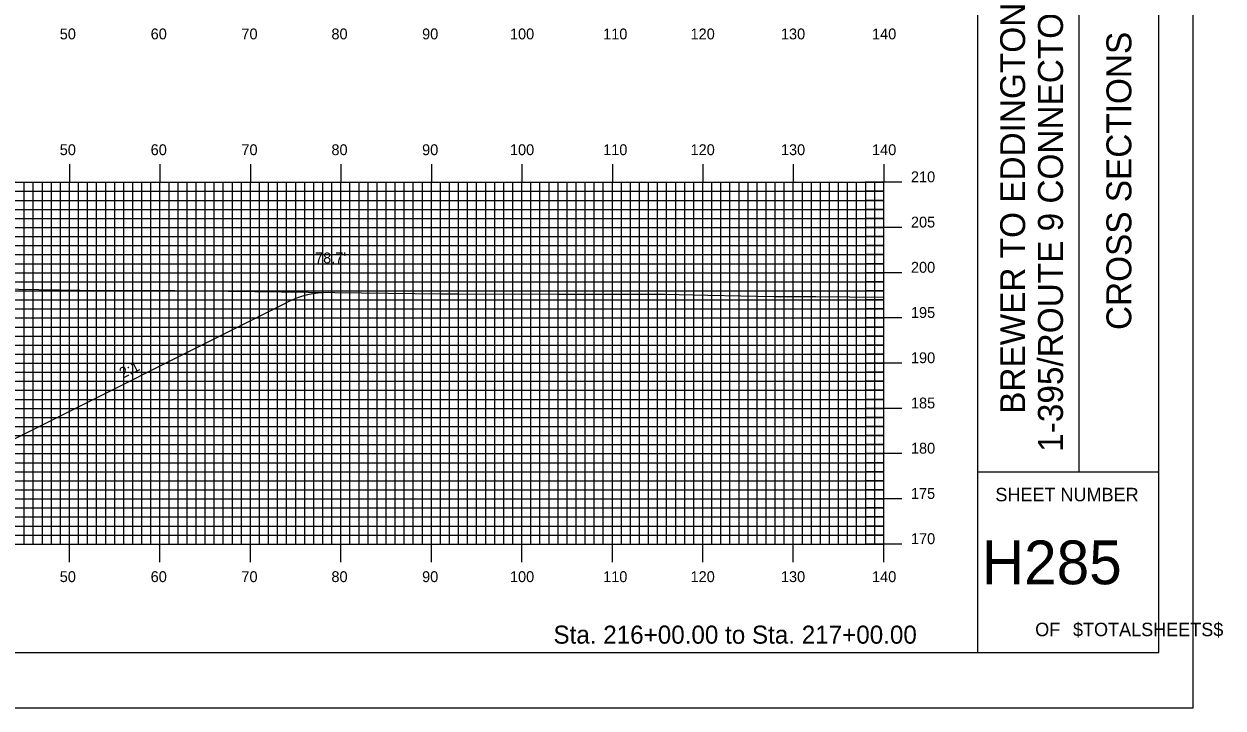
# Model space of a CAD drawing. Extents: x 1796420 to 1796763, y 442591 to 442811.
# Drawn here: x 1796630.9 to 1796763.4, y 442590.5 to 442666.2 of the extents above; entities that cross this region are included whole.
import ezdxf

# ---------------------------------------------------------------- set-up
doc = ezdxf.new("R2010")
doc.units = 0
for name, color, linetype in [('ANNOTATION', 7, 'Continuous'), ('BORDER', 7, 'Continuous'), ('D_Roadway_SlopeLines', 7, 'Continuous'), ('D_Text_Standard', 7, 'Continuous'), ('H_V ANNOTATION', 7, 'Continuous'), ('MAJOR', 7, 'Continuous'), ('MINOR', 7, 'Continuous'), ('PLOT BOUNDARY', 7, 'Continuous'), ('S_Roadway_Centerline', 7, 'Continuous')]:
    doc.layers.add(name, color=color, linetype=linetype)

msp = doc.modelspace()

# ---------------------------------------------------------------- linework, layer by layer
at = {"layer": 'ANNOTATION'}
msp.add_line((1796725.91, 442628.67), (1796725.91, 442629.27), dxfattribs=at)
msp.add_arc((1796664.49, 442626.48), 10, 89.621, 116.5651, dxfattribs=at)
msp.add_arc((1796664.49, 442626.48), 10, 89.621, 116.5651, dxfattribs=at)
at = {"layer": 'BORDER'}
for p, q in [((1796736.31, 442596.67), (1796736.31, 442806.67)), ((1796747.49, 442616.67), (1796747.49, 442686.67)), ((1796736.31, 442616.67), (1796756.31, 442616.67))]:
    msp.add_line(p, q, dxfattribs=at)
msp.add_lwpolyline([(1796436.31, 442596.67), (1796756.31, 442596.67), (1796756.31, 442806.67), (1796436.31, 442806.67)], close=True, dxfattribs=at)
at = {"layer": 'D_Roadway_SlopeLines'}
msp.add_lwpolyline([(1796621.3, 442619.07), (1796627.3, 442619.07), (1796660.02, 442635.43)], dxfattribs=at)
at = {"layer": 'MAJOR'}
for p, q in [((1796635.91, 442650.67), (1796635.91, 442648.67)), ((1796645.91, 442650.67), (1796645.91, 442648.67)), ((1796655.91, 442650.67), (1796655.91, 442648.67)), ((1796665.91, 442650.67), (1796665.91, 442648.67)), ((1796675.91, 442650.67), (1796675.91, 442648.67)), ((1796685.91, 442650.67), (1796685.91, 442648.67)), ((1796695.91, 442650.67), (1796695.91, 442648.67)), ((1796705.91, 442650.67), (1796705.91, 442648.67)), ((1796715.91, 442650.67), (1796715.91, 442648.67)), ((1796725.91, 442650.67), (1796725.91, 442648.67)), ((1796445.91, 442648.67), (1796725.91, 442648.67)), ((1796445.91, 442648.67), (1796725.91, 442648.67)), ((1796635.91, 442608.67), (1796635.91, 442648.67)), ((1796645.91, 442608.67), (1796645.91, 442648.67)), ((1796655.91, 442608.67), (1796655.91, 442648.67)), ((1796665.91, 442608.67), (1796665.91, 442648.67)), ((1796675.91, 442608.67), (1796675.91, 442648.67)), ((1796685.91, 442608.67), (1796685.91, 442648.67)), ((1796695.91, 442608.67), (1796695.91, 442648.67)), ((1796705.91, 442608.67), (1796705.91, 442648.67)), ((1796715.91, 442608.67), (1796715.91, 442648.67)), ((1796727.91, 442648.67), (1796723.9, 442648.67)), ((1796725.91, 442608.67), (1796725.91, 442648.67)), ((1796725.91, 442608.67), (1796725.91, 442648.67)), ((1796445.91, 442643.67), (1796725.91, 442643.67)), ((1796727.91, 442643.67), (1796723.9, 442643.67)), ((1796445.91, 442638.67), (1796725.91, 442638.67)), ((1796727.91, 442638.67), (1796723.9, 442638.67)), ((1796445.91, 442633.67), (1796725.91, 442633.67)), ((1796727.91, 442633.67), (1796723.9, 442633.67)), ((1796445.91, 442628.67), (1796725.91, 442628.67)), ((1796727.91, 442628.67), (1796723.9, 442628.67)), ((1796445.91, 442623.67), (1796725.91, 442623.67)), ((1796727.91, 442623.67), (1796723.9, 442623.67)), ((1796445.91, 442618.67), (1796725.91, 442618.67)), ((1796727.91, 442618.67), (1796723.9, 442618.67)), ((1796445.91, 442613.67), (1796725.91, 442613.67)), ((1796727.91, 442613.67), (1796723.9, 442613.67)), ((1796445.91, 442608.67), (1796725.91, 442608.67)), ((1796445.91, 442608.67), (1796725.91, 442608.67)), ((1796635.91, 442606.66), (1796635.91, 442608.67)), ((1796645.91, 442606.66), (1796645.91, 442608.67)), ((1796655.91, 442606.66), (1796655.91, 442608.67)), ((1796665.91, 442606.66), (1796665.91, 442608.67)), ((1796675.91, 442606.66), (1796675.91, 442608.67)), ((1796685.91, 442606.66), (1796685.91, 442608.67)), ((1796695.91, 442606.66), (1796695.91, 442608.67)), ((1796705.91, 442606.66), (1796705.91, 442608.67)), ((1796715.91, 442606.66), (1796715.91, 442608.67)), ((1796727.91, 442608.67), (1796723.9, 442608.67)), ((1796725.91, 442606.66), (1796725.91, 442608.67))]:
    msp.add_line(p, q, dxfattribs=at)
at = {"layer": 'MINOR'}
for p, q in [((1796630.91, 442608.67), (1796630.91, 442648.67)), ((1796631.91, 442608.67), (1796631.91, 442648.67)), ((1796632.91, 442608.67), (1796632.91, 442648.67)), ((1796633.91, 442608.67), (1796633.91, 442648.67)), ((1796634.91, 442608.67), (1796634.91, 442648.67)), ((1796636.91, 442608.67), (1796636.91, 442648.67)), ((1796637.91, 442608.67), (1796637.91, 442648.67)), ((1796638.91, 442608.67), (1796638.91, 442648.67)), ((1796639.91, 442608.67), (1796639.91, 442648.67)), ((1796640.91, 442608.67), (1796640.91, 442648.67)), ((1796641.91, 442608.67), (1796641.91, 442648.67)), ((1796642.91, 442608.67), (1796642.91, 442648.67)), ((1796643.91, 442608.67), (1796643.91, 442648.67)), ((1796644.91, 442608.67), (1796644.91, 442648.67)), ((1796646.91, 442608.67), (1796646.91, 442648.67)), ((1796647.91, 442608.67), (1796647.91, 442648.67)), ((1796648.91, 442608.67), (1796648.91, 442648.67)), ((1796649.91, 442608.67), (1796649.91, 442648.67)), ((1796650.91, 442608.67), (1796650.91, 442648.67)), ((1796651.91, 442608.67), (1796651.91, 442648.67)), ((1796652.91, 442608.67), (1796652.91, 442648.67)), ((1796653.91, 442608.67), (1796653.91, 442648.67)), ((1796654.91, 442608.67), (1796654.91, 442648.67)), ((1796656.91, 442608.67), (1796656.91, 442648.67)), ((1796657.91, 442608.67), (1796657.91, 442648.67)), ((1796658.91, 442608.67), (1796658.91, 442648.67)), ((1796659.91, 442608.67), (1796659.91, 442648.67)), ((1796660.91, 442608.67), (1796660.91, 442648.67)), ((1796661.91, 442608.67), (1796661.91, 442648.67)), ((1796662.91, 442608.67), (1796662.91, 442648.67)), ((1796663.91, 442608.67), (1796663.91, 442648.67)), ((1796664.91, 442608.67), (1796664.91, 442648.67)), ((1796666.91, 442608.67), (1796666.91, 442648.67)), ((1796667.91, 442608.67), (1796667.91, 442648.67)), ((1796668.91, 442608.67), (1796668.91, 442648.67)), ((1796669.91, 442608.67), (1796669.91, 442648.67)), ((1796670.91, 442608.67), (1796670.91, 442648.67)), ((1796671.91, 442608.67), (1796671.91, 442648.67)), ((1796672.91, 442608.67), (1796672.91, 442648.67)), ((1796673.91, 442608.67), (1796673.91, 442648.67)), ((1796674.91, 442608.67), (1796674.91, 442648.67)), ((1796676.91, 442608.67), (1796676.91, 442648.67)), ((1796677.91, 442608.67), (1796677.91, 442648.67)), ((1796678.91, 442608.67), (1796678.91, 442648.67)), ((1796679.91, 442608.67), (1796679.91, 442648.67)), ((1796680.91, 442608.67), (1796680.91, 442648.67)), ((1796681.91, 442608.67), (1796681.91, 442648.67)), ((1796682.91, 442608.67), (1796682.91, 442648.67)), ((1796683.91, 442608.67), (1796683.91, 442648.67)), ((1796684.91, 442608.67), (1796684.91, 442648.67)), ((1796686.91, 442608.67), (1796686.91, 442648.67)), ((1796687.91, 442608.67), (1796687.91, 442648.67)), ((1796688.91, 442608.67), (1796688.91, 442648.67)), ((1796689.91, 442608.67), (1796689.91, 442648.67)), ((1796690.91, 442608.67), (1796690.91, 442648.67)), ((1796691.91, 442608.67), (1796691.91, 442648.67)), ((1796692.91, 442608.67), (1796692.91, 442648.67)), ((1796693.91, 442608.67), (1796693.91, 442648.67)), ((1796694.91, 442608.67), (1796694.91, 442648.67)), ((1796696.91, 442608.67), (1796696.91, 442648.67)), ((1796697.91, 442608.67), (1796697.91, 442648.67)), ((1796698.91, 442608.67), (1796698.91, 442648.67)), ((1796699.91, 442608.67), (1796699.91, 442648.67)), ((1796700.91, 442608.67), (1796700.91, 442648.67)), ((1796701.91, 442608.67), (1796701.91, 442648.67)), ((1796702.91, 442608.67), (1796702.91, 442648.67)), ((1796703.91, 442608.67), (1796703.91, 442648.67)), ((1796704.91, 442608.67), (1796704.91, 442648.67)), ((1796706.91, 442608.67), (1796706.91, 442648.67)), ((1796707.91, 442608.67), (1796707.91, 442648.67)), ((1796708.91, 442608.67), (1796708.91, 442648.67)), ((1796709.91, 442608.67), (1796709.91, 442648.67)), ((1796710.91, 442608.67), (1796710.91, 442648.67)), ((1796711.91, 442608.67), (1796711.91, 442648.67)), ((1796712.91, 442608.67), (1796712.91, 442648.67)), ((1796713.91, 442608.67), (1796713.91, 442648.67)), ((1796714.91, 442608.67), (1796714.91, 442648.67)), ((1796716.91, 442608.67), (1796716.91, 442648.67)), ((1796717.91, 442608.67), (1796717.91, 442648.67)), ((1796718.91, 442608.67), (1796718.91, 442648.67)), ((1796719.91, 442608.67), (1796719.91, 442648.67)), ((1796720.91, 442608.67), (1796720.91, 442648.67)), ((1796721.91, 442608.67), (1796721.91, 442648.67)), ((1796722.91, 442608.67), (1796722.91, 442648.67)), ((1796723.91, 442608.67), (1796723.91, 442648.67)), ((1796724.91, 442608.67), (1796724.91, 442648.67)), ((1796445.91, 442647.67), (1796725.91, 442647.67)), ((1796725.91, 442647.67), (1796723.9, 442647.67)), ((1796445.91, 442646.67), (1796725.91, 442646.67)), ((1796725.91, 442646.67), (1796723.9, 442646.67)), ((1796445.91, 442645.67), (1796725.91, 442645.67)), ((1796725.91, 442645.67), (1796723.9, 442645.67)), ((1796445.91, 442644.67), (1796725.91, 442644.67)), ((1796725.91, 442644.67), (1796723.9, 442644.67)), ((1796445.91, 442642.67), (1796725.91, 442642.67)), ((1796725.91, 442642.67), (1796723.9, 442642.67)), ((1796445.91, 442641.67), (1796725.91, 442641.67)), ((1796725.91, 442641.67), (1796723.9, 442641.67)), ((1796445.91, 442640.67), (1796725.91, 442640.67)), ((1796445.91, 442639.67), (1796725.91, 442639.67)), ((1796725.91, 442640.67), (1796723.9, 442640.67)), ((1796725.91, 442639.67), (1796723.9, 442639.67)), ((1796445.91, 442637.67), (1796725.91, 442637.67)), ((1796725.91, 442637.67), (1796723.9, 442637.67)), ((1796445.91, 442636.67), (1796725.91, 442636.67)), ((1796445.91, 442635.67), (1796725.91, 442635.67)), ((1796725.91, 442636.67), (1796723.9, 442636.67)), ((1796725.91, 442635.67), (1796723.9, 442635.67)), ((1796445.91, 442634.67), (1796725.91, 442634.67)), ((1796725.91, 442634.67), (1796723.9, 442634.67)), ((1796445.91, 442632.67), (1796725.91, 442632.67)), ((1796445.91, 442631.67), (1796725.91, 442631.67)), ((1796725.91, 442632.67), (1796723.9, 442632.67)), ((1796725.91, 442631.67), (1796723.9, 442631.67)), ((1796445.91, 442630.67), (1796725.91, 442630.67)), ((1796725.91, 442630.67), (1796723.9, 442630.67)), ((1796445.91, 442629.67), (1796725.91, 442629.67)), ((1796725.91, 442629.67), (1796723.9, 442629.67)), ((1796445.91, 442627.67), (1796725.91, 442627.67)), ((1796725.91, 442627.67), (1796723.9, 442627.67)), ((1796445.91, 442626.67), (1796725.91, 442626.67)), ((1796725.91, 442626.67), (1796723.9, 442626.67)), ((1796445.91, 442625.67), (1796725.91, 442625.67)), ((1796725.91, 442625.67), (1796723.9, 442625.67)), ((1796445.91, 442624.67), (1796725.91, 442624.67)), ((1796725.91, 442624.67), (1796723.9, 442624.67)), ((1796445.91, 442622.67), (1796725.91, 442622.67)), ((1796725.91, 442622.67), (1796723.9, 442622.67)), ((1796445.91, 442621.67), (1796725.91, 442621.67)), ((1796725.91, 442621.67), (1796723.9, 442621.67)), ((1796445.91, 442620.67), (1796725.91, 442620.67)), ((1796445.91, 442619.67), (1796725.91, 442619.67)), ((1796725.91, 442620.67), (1796723.9, 442620.67)), ((1796725.91, 442619.67), (1796723.9, 442619.67)), ((1796445.91, 442617.67), (1796725.91, 442617.67)), ((1796725.91, 442617.67), (1796723.9, 442617.67)), ((1796445.91, 442616.67), (1796725.91, 442616.67)), ((1796445.91, 442615.67), (1796725.91, 442615.67)), ((1796725.91, 442616.67), (1796723.9, 442616.67)), ((1796725.91, 442615.67), (1796723.9, 442615.67)), ((1796445.91, 442614.67), (1796725.91, 442614.67)), ((1796725.91, 442614.67), (1796723.9, 442614.67)), ((1796445.91, 442612.67), (1796725.91, 442612.67)), ((1796445.91, 442611.67), (1796725.91, 442611.67)), ((1796725.91, 442612.67), (1796723.9, 442612.67)), ((1796725.91, 442611.67), (1796723.9, 442611.67)), ((1796445.91, 442610.67), (1796725.91, 442610.67)), ((1796725.91, 442610.67), (1796723.9, 442610.67)), ((1796445.91, 442609.67), (1796725.91, 442609.67)), ((1796725.91, 442609.67), (1796723.9, 442609.67))]:
    msp.add_line(p, q, dxfattribs=at)
at = {"layer": 'PLOT BOUNDARY'}
msp.add_lwpolyline([(1796420.12, 442590.55), (1796760.12, 442590.55), (1796760.12, 442810.55), (1796420.12, 442810.55)], close=True, dxfattribs=at)
at = {"layer": 'S_Roadway_Centerline'}
msp.add_lwpolyline([(1796621.2, 442636.99), (1796639.28, 442636.72), (1796642.75, 442636.73), (1796647.54, 442636.69), (1796659.34, 442636.55), (1796677.02, 442636.33), (1796678.85, 442636.32), (1796689.93, 442636.31), (1796698.54, 442636.3), (1796701.72, 442636.3), (1796706.47, 442636.2), (1796713.74, 442636.05), (1796718.41, 442636.04), (1796725.91, 442635.98)], dxfattribs=at)

# ---------------------------------------------------------------- texts
at = {"layer": 'ANNOTATION'}
msp.add_text('2:1', height=1.2, rotation=26.5651, dxfattribs=at).set_placement((1796641.79, 442626.95))
msp.add_text('2:1', height=1.2, rotation=26.5651, dxfattribs=at).set_placement((1796641.79, 442626.95))
at = {"layer": 'BORDER'}
for s, p in [('1-395/ROUTE 9 CONNECTOR', (1796745.71, 442618.87)), ('BREWER TO EDDINGTON', (1796741.53, 442623.07)), ('CROSS SECTIONS', (1796753.27, 442632.34))]:
    msp.add_text(s, height=2.7557, rotation=90, dxfattribs=at).set_placement(p)
for s, height, p in [('SHEET NUMBER', 1.4905, (1796738.24, 442613.4)), ('H285', 4.839, (1796736.74, 442604.23)), ('OF', 1.491, (1796742.64, 442598.49)), ('$TOTALSHEETS$', 1.4905, (1796746.82, 442598.49))]:
    msp.add_text(s, height=height, dxfattribs=at).set_placement(p)
at = {"layer": 'D_Text_Standard'}
msp.add_text("78.7'", height=1.2, dxfattribs=at).set_placement((1796663.05, 442639.71))
at = {"layer": 'H_V ANNOTATION'}
for s, height, p in [('50', 1.2, (1796634.83, 442664.47)), ('60', 1.2, (1796644.88, 442664.47)), ('70', 1.2, (1796654.91, 442664.47)), ('80', 1.2, (1796664.86, 442664.47)), ('90', 1.2, (1796674.88, 442664.47)), ('100', 1.2, (1796684.59, 442664.47)), ('110', 1.2, (1796694.89, 442664.47)), ('120', 1.2, (1796704.55, 442664.47)), ('130', 1.2, (1796714.54, 442664.47)), ('140', 1.2, (1796724.61, 442664.47)), ('50', 1.2, (1796634.83, 442651.67)), ('60', 1.2, (1796644.88, 442651.67)), ('70', 1.2, (1796654.91, 442651.67)), ('80', 1.2, (1796664.86, 442651.67)), ('90', 1.2, (1796674.88, 442651.67)), ('100', 1.2, (1796684.59, 442651.67)), ('110', 1.2, (1796694.89, 442651.67)), ('120', 1.2, (1796704.55, 442651.67)), ('130', 1.2, (1796714.54, 442651.67)), ('140', 1.2, (1796724.61, 442651.67)), ('210', 1.2, (1796728.91, 442648.67)), ('205', 1.2, (1796728.91, 442643.67)), ('200', 1.2, (1796728.91, 442638.67)), ('195', 1.2, (1796728.91, 442633.67)), ('190', 1.2, (1796728.91, 442628.67)), ('185', 1.2, (1796728.91, 442623.67)), ('180', 1.2, (1796728.91, 442618.67)), ('175', 1.2, (1796728.91, 442613.67)), ('170', 1.2, (1796728.91, 442608.67)), ('50', 1.2, (1796634.83, 442604.47)), ('60', 1.2, (1796644.88, 442604.47)), ('70', 1.2, (1796654.91, 442604.47)), ('80', 1.2, (1796664.86, 442604.47)), ('90', 1.2, (1796674.88, 442604.47)), ('100', 1.2, (1796684.59, 442604.47)), ('110', 1.2, (1796694.89, 442604.47)), ('120', 1.2, (1796704.55, 442604.47)), ('130', 1.2, (1796714.54, 442604.47)), ('140', 1.2, (1796724.61, 442604.47)), ('Sta. 216+00.00 to Sta. 217+00.00', 2.0004, (1796689.4, 442597.66))]:
    msp.add_text(s, height=height, dxfattribs=at).set_placement(p)

doc.saveas('drawing.dxf')
